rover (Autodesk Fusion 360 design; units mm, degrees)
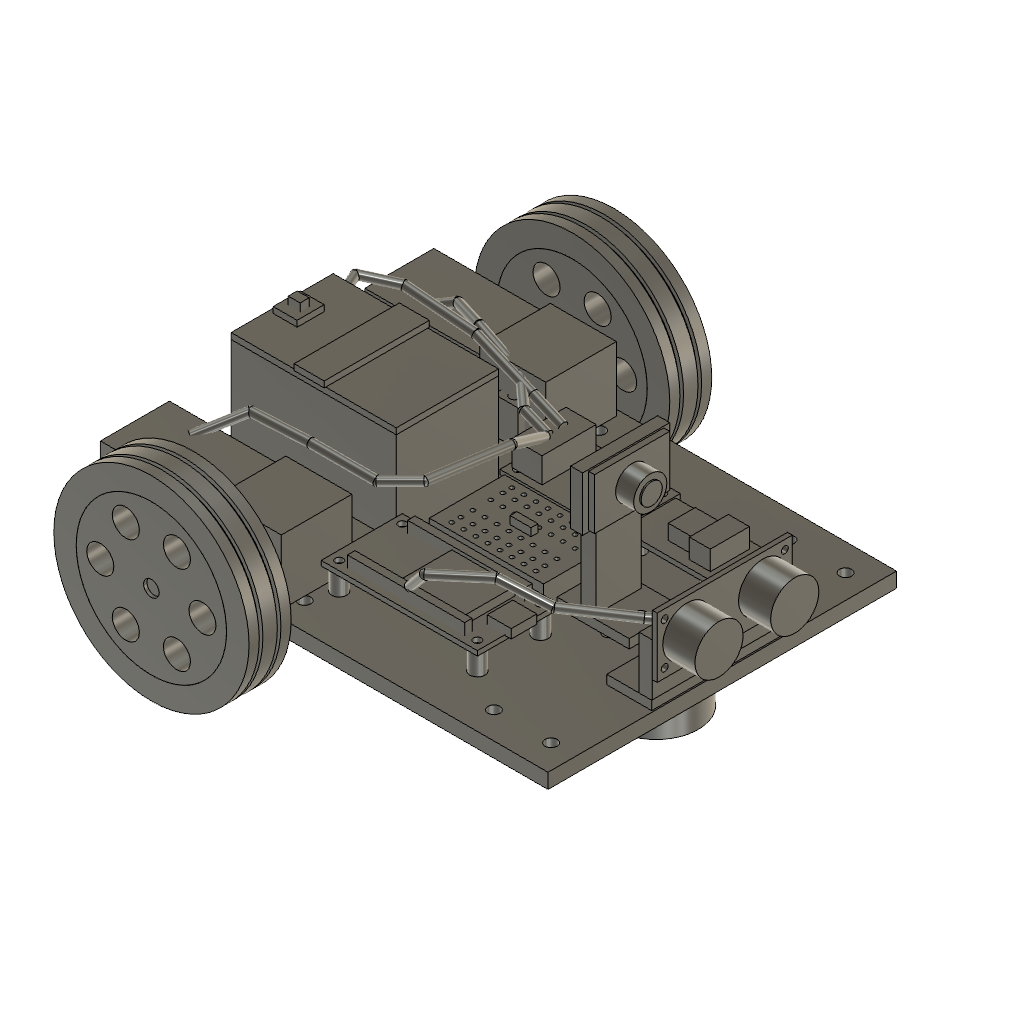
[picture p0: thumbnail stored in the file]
part number: 2026-11-24-23-59-55-931
part number: 2026-11-24-23-59-56-019
part number: 2026-11-24-23-59-56-042
part number: 2026-11-24-23-59-56-065
part number: 2026-11-24-23-59-56-098
part number: 2026-11-24-23-59-56-124
part number: 2026-11-24-23-59-56-158
part number: 2026-11-24-23-59-56-183
part number: 2026-11-24-23-59-56-213
part number: 2026-11-24-23-59-56-244
part number: 2026-11-24-23-59-56-284
part number: 2026-11-24-23-59-56-312
part number: 2026-11-24-23-59-56-339
part number: 2026-11-24-23-59-56-373
base_feature "Base Feature1" bodies "Chassis plate with mounting holes"
ground "Pin"
base_feature "Base Feature1" bodies "TT gearmotor envelope", "Gearbox end cover", "Motor mounting saddle", "Drive shaft"
base_feature "Base Feature1" bodies "65 mm tire with tread grooves", "Wheel hub with vent holes"
as_built_joint "As-built1" bodies "Driver board standoff (2)"
sketch "Left wheel rotation pivot reference" plane through (0, 0, 0) normal (0, 0, 1) x axis (1, 0, 0)
as_built_joint "As-built2" bodies "Driver board standoff (2)"
base_feature "Base Feature1" bodies "TT gearmotor envelope", "Gearbox end cover", "Motor mounting saddle", "Drive shaft"
base_feature "Base Feature1" bodies "65 mm tire with tread grooves", "Wheel hub with vent holes"
as_built_joint "As-built3"
sketch "Right wheel rotation pivot reference" plane through (0, 0, 0) normal (0, 0, 1) x axis (1, 0, 0)
as_built_joint "As-built4" bodies "Driver board standoff (2)"
base_feature "Base Feature1" bodies "Caster mounting flange", "Ball caster housing", "20 mm caster ball"
base_feature "Base Feature1" bodies "4 x AA holder enclosure", "Battery cover", "Switch housing", "Slide switch", "Battery strap"
base_feature "Base Feature1" bodies "ESP32 board envelope", "Radio shield", "USB connector", "Pin header A", "Pin header B", "Controller standoff", "Controller standoff (1)", "Controller standoff (2)"
base_feature "Base Feature1" bodies "Pmod DHB1 board envelope", "Driver terminal block", "Motor driver power chip", "Regulator board envelope", "Regulator inductor", "Regulator screw terminal", "Driver board standoff", "Driver board standoff (1)"
base_feature "Base Feature1" bodies "Mini breadboard envelope with socket rows", "Central divider resistor envelope"
base_feature "Base Feature1" bodies "Sensor board envelope", "Left ultrasonic transducer", "Right ultrasonic transducer", "Sensor wire header", "Mount foot", "Upright sensor support"
base_feature "Base Feature1" bodies "Camera mounting foot", "Camera upright", "Camera mounting plate", "Camera board envelope", "Lens barrel", "Lens recess"
base_feature "Base Feature1" bodies "Battery feed to driver", "Left motor lead", "Right motor lead", "ESP32 to sensor jumper"
as_built_joint "As-built5"
as_built_joint "As-built6"
as_built_joint "As-built7"
as_built_joint "As-built8"
as_built_joint "As-built9"
as_built_joint "As-built10"
as_built_joint "As-built11"
as_built_joint "As-built12"
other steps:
create_component "CreateComponent1"
create_component "CreateComponent2"
create_component "CreateComponent3"
create_component "CreateComponent4"
create_component "CreateComponent5"
create_component "CreateComponent6"
create_component "CreateComponent7"
create_component "CreateComponent8"
create_component "CreateComponent9"
create_component "CreateComponent10"
create_component "CreateComponent11"
create_component "CreateComponent12"
create_component "CreateComponent13"
named bodies: "Chassis plate with mounting holes", "TT gearmotor envelope", "Gearbox end cover", "Motor mounting saddle", "Drive shaft", "65 mm tire with tread grooves", "Wheel hub with vent holes", "Caster mounting flange", "Ball caster housing", "20 mm caster ball", "4 x AA holder enclosure", "Battery cover", "Switch housing", "Slide switch", "Battery strap", "ESP32 board envelope", "Radio shield", "USB connector", "Pin header A", "Pin header B", "Controller standoff", "Controller standoff (1)", "Controller standoff (2)", "Controller standoff (3)", "Pmod DHB1 board envelope", "Driver terminal block", "Motor driver power chip", "Regulator board envelope", "Regulator inductor", "Regulator screw terminal", "Driver board standoff", "Driver board standoff (1)", "Driver board standoff (2)", "Driver board standoff (3)", "Driver board standoff (4)", "Driver board standoff (5)", "Driver board standoff (6)", "Driver board standoff (7)", "Mini breadboard envelope with socket rows", "Central divider resistor envelope", "Sensor board envelope", "Left ultrasonic transducer", "Right ultrasonic transducer", "Sensor wire header", "Mount foot", "Upright sensor support", "Camera mounting foot", "Camera upright", "Camera mounting plate", "Camera board envelope", "Lens barrel", "Lens recess", "Battery feed to driver", "Left motor lead", "Right motor lead", "ESP32 to sensor jumper"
